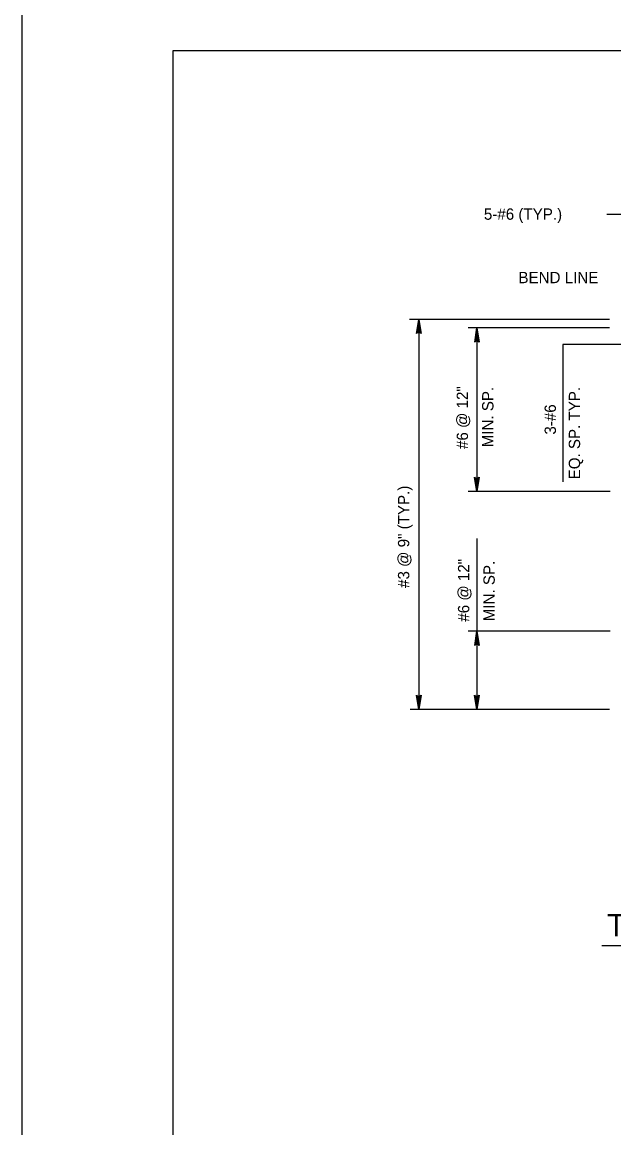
# Model space of a CAD drawing. Extents: x 639011 to 639866, y 298840 to 300028.
# Drawn here: x 639011.3 to 639168.1, y 299133.1 to 299426.3 of the extents above; entities that cross this region are included whole.
import ezdxf

# ---------------------------------------------------------------- set-up
doc = ezdxf.new("R2010")
doc.units = 0
doc.layers.add('2', color=7, linetype='Continuous')
doc.layers.add('PLT-BNDY', color=7, linetype='Continuous')

msp = doc.modelspace()

# ---------------------------------------------------------------- linework, layer by layer
at = {"layer": '2'}
for p, q in [((639051.26, 298854.83), (639051.26, 299418.83)), ((639051.26, 299418.83), (639837.26, 299418.83)), ((639166.21, 299375.41), (639184.93, 299375.41)), ((639166.89, 299347.51), (639113.89, 299347.51)), ((639115.78, 299343.71), (639116.37, 299347.51)), ((639116.37, 299347.51), (639115.94, 299343.9)), ((639116.2, 299344.03), (639116.37, 299347.51)), ((639116.37, 299347.51), (639116.37, 299244.01)), ((639116.37, 299347.51), (639116.56, 299344.04)), ((639116.83, 299343.91), (639116.37, 299347.51)), ((639116.37, 299347.51), (639117, 299343.71)), ((639116.37, 299347.51), (639116.38, 299344.04)), ((639115.94, 299343.9), (639115.78, 299343.71)), ((639115.94, 299343.9), (639116.2, 299344.03)), ((639116.2, 299344.03), (639116.56, 299344.04)), ((639116.56, 299344.04), (639116.83, 299343.91)), ((639117, 299343.71), (639116.83, 299343.91)), ((639166.89, 299345.26), (639129.49, 299345.26)), ((639131.18, 299341.46), (639131.77, 299345.26)), ((639131.77, 299345.26), (639131.34, 299341.65)), ((639131.6, 299341.78), (639131.77, 299345.26)), ((639131.77, 299345.26), (639131.77, 299301.83)), ((639131.77, 299345.26), (639131.96, 299341.79)), ((639132.23, 299341.66), (639131.77, 299345.26)), ((639131.77, 299345.26), (639132.4, 299341.46)), ((639131.77, 299345.26), (639131.78, 299341.79)), ((639131.34, 299341.65), (639131.18, 299341.46)), ((639131.34, 299341.65), (639131.6, 299341.78)), ((639131.6, 299341.78), (639131.96, 299341.79)), ((639131.96, 299341.79), (639132.23, 299341.66)), ((639132.4, 299341.46), (639132.23, 299341.66)), ((639154.57, 299340.83), (639154.57, 299304.44)), ((639176.52, 299340.83), (639154.57, 299340.83)), ((639131.77, 299301.83), (639131.13, 299305.63)), ((639131.13, 299305.63), (639131.31, 299305.43)), ((639132.36, 299305.64), (639131.77, 299301.83)), ((639132.2, 299305.44), (639132.36, 299305.64)), ((639131.57, 299305.31), (639131.31, 299305.43)), ((639131.31, 299305.43), (639131.77, 299301.83)), ((639131.77, 299301.83), (639131.57, 299305.31)), ((639131.93, 299305.31), (639131.57, 299305.31)), ((639131.77, 299301.83), (639131.75, 299305.31)), ((639131.77, 299301.83), (639132.2, 299305.44)), ((639131.93, 299305.31), (639131.77, 299301.83)), ((639132.2, 299305.44), (639131.93, 299305.31)), ((639167.09, 299301.83), (639129.49, 299301.83)), ((639131.77, 299289.39), (639131.77, 299244.01)), ((639167.09, 299264.84), (639129.49, 299264.84)), ((639131.18, 299261.04), (639131.77, 299264.84)), ((639131.77, 299264.84), (639131.34, 299261.23)), ((639131.6, 299261.37), (639131.77, 299264.84)), ((639131.77, 299264.84), (639131.96, 299261.37)), ((639132.23, 299261.24), (639131.77, 299264.84)), ((639131.77, 299264.84), (639132.4, 299261.05)), ((639131.77, 299264.84), (639131.78, 299261.37)), ((639131.34, 299261.23), (639131.18, 299261.04)), ((639131.34, 299261.23), (639131.6, 299261.37)), ((639131.6, 299261.37), (639131.96, 299261.37)), ((639131.96, 299261.37), (639132.23, 299261.24)), ((639132.4, 299261.05), (639132.23, 299261.24)), ((639116.37, 299244.01), (639115.73, 299247.8)), ((639115.73, 299247.8), (639115.91, 299247.61)), ((639116.17, 299247.48), (639115.91, 299247.61)), ((639115.91, 299247.61), (639116.37, 299244.01)), ((639116.37, 299244.01), (639116.17, 299247.48)), ((639116.53, 299247.48), (639116.17, 299247.48)), ((639116.37, 299244.01), (639116.35, 299247.48)), ((639116.96, 299247.81), (639116.37, 299244.01)), ((639116.37, 299244.01), (639116.8, 299247.62)), ((639116.53, 299247.48), (639116.37, 299244.01)), ((639116.8, 299247.62), (639116.53, 299247.48)), ((639116.8, 299247.62), (639116.96, 299247.81)), ((639131.77, 299244.01), (639131.13, 299247.8)), ((639131.13, 299247.8), (639131.31, 299247.61)), ((639131.57, 299247.48), (639131.31, 299247.61)), ((639131.31, 299247.61), (639131.77, 299244.01)), ((639131.77, 299244.01), (639131.57, 299247.48)), ((639131.93, 299247.48), (639131.57, 299247.48)), ((639131.77, 299244.01), (639131.75, 299247.48)), ((639132.36, 299247.81), (639131.77, 299244.01)), ((639131.77, 299244.01), (639132.2, 299247.62)), ((639131.93, 299247.48), (639131.77, 299244.01)), ((639132.2, 299247.62), (639131.93, 299247.48)), ((639132.2, 299247.62), (639132.36, 299247.81)), ((639166.89, 299244.01), (639114.09, 299244.01)), ((639164.88, 299181.42), (639320.19, 299181.42))]:
    msp.add_line(p, q, dxfattribs=at)
at = {"layer": 'PLT-BNDY'}
msp.add_lwpolyline([(639011.26, 299433.83), (639852.26, 299433.83), (639852.26, 298839.83), (639011.26, 298839.83)], close=True, dxfattribs=at)

# ---------------------------------------------------------------- texts
at = {"layer": '2'}
for s, height, p in [('5-#6 (TYP.)', 3, (639133.62, 299373.92)), ('BEND LINE', 3, (639142.78, 299357.1)), ('TYPICAL HEADWALL ELEVATION', 6, (639166.26, 299183.84))]:
    msp.add_text(s, height=height, dxfattribs=at).set_placement(p)
for s, p in [('#6 @ 12"', (639129.41, 299313.12)), ('MIN. SP.', (639136.16, 299313.57)), ('EQ. SP. TYP.', (639159.12, 299305.07)), ('3-#6', (639152.71, 299316.94)), ('#3 @ 9" (TYP.)', (639113.85, 299276.28)), ('#6 @ 12"', (639129.75, 299267.32)), ('MIN. SP.', (639136.5, 299267.44))]:
    msp.add_text(s, height=3, rotation=90, dxfattribs=at).set_placement(p)

doc.saveas('drawing.dxf')
